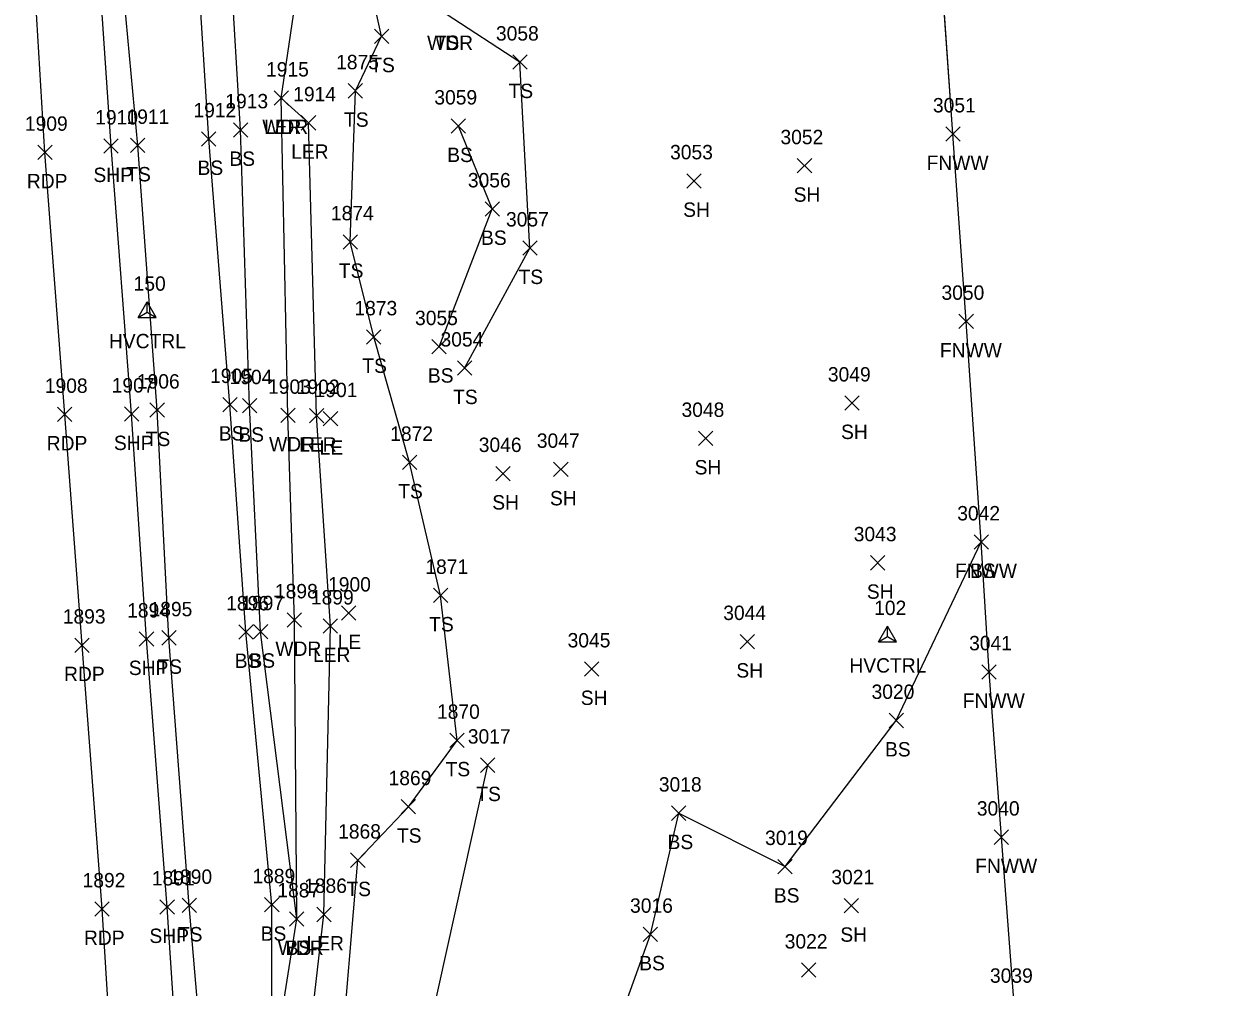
# Model space of a CAD drawing. Extents: x 1650221 to 1650634, y 244606 to 249996.
# Drawn here: x 1650455.2 to 1650620.5, y 244998.2 to 245132.2 of the extents above; entities that cross this region are included whole.
import ezdxf

# ---------------------------------------------------------------- set-up
doc = ezdxf.new("R2010")
doc.units = 0
for name, color, linetype in [('C_A', 7, 'Continuous'), ('C_I', 7, 'Continuous'), ('CPSM', 7, 'Continuous'), ('L_A', 7, 'Continuous'), ('L_I', 7, 'Continuous'), ('L_TIC', 7, 'Continuous'), ('LARO', 7, 'Continuous'), ('LAWA', 7, 'Continuous'), ('LELB', 7, 'Continuous'), ('LFNC', 7, 'Continuous'), ('LSOGP', 7, 'Continuous'), ('P_A', 7, 'Continuous'), ('P_I', 7, 'Continuous'), ('P_TIC', 7, 'Continuous'), ('PET', 7, 'Continuous'), ('PSP', 7, 'Continuous')]:
    doc.layers.add(name, color=color, linetype=linetype)

msp = doc.modelspace()

# ---------------------------------------------------------------- linework, layer by layer
at = {"layer": 'CPSM'}
for p, q in [((1650471.11, 245091.36), (1650472.36, 245093.53)), ((1650473.61, 245091.36), (1650472.36, 245093.53)), ((1650472.36, 245092.08), (1650472.36, 245093.53)), ((1650471.11, 245091.36), (1650472.36, 245092.08)), ((1650471.11, 245091.36), (1650473.61, 245091.36)), ((1650472.36, 245092.08), (1650472.36, 245092.08)), ((1650472.36, 245092.08), (1650473.61, 245091.36)), ((1650574.01, 245046.27), (1650575.26, 245048.43)), ((1650576.51, 245046.27), (1650575.26, 245048.43)), ((1650575.26, 245046.99), (1650575.26, 245048.43)), ((1650574.01, 245046.27), (1650575.26, 245046.99)), ((1650575.26, 245046.99), (1650575.26, 245046.99)), ((1650575.26, 245046.99), (1650576.51, 245046.27)), ((1650574.01, 245046.27), (1650576.51, 245046.27))]:
    msp.add_line(p, q, dxfattribs=at)
at = {"layer": 'L_TIC'}
for points in [[(1650503.95, 245129.46), (1650505.95, 245131.46)], [(1650505.95, 245129.46), (1650503.95, 245131.46)], [(1650523.17, 245125.86), (1650525.17, 245127.86)], [(1650525.17, 245125.86), (1650523.17, 245127.86)], [(1650490, 245120.86), (1650492, 245122.86)], [(1650492, 245120.86), (1650490, 245122.86)], [(1650490, 245120.86), (1650492, 245122.86)], [(1650492, 245120.86), (1650490, 245122.86)], [(1650500.31, 245121.87), (1650502.31, 245123.87)], [(1650502.31, 245121.87), (1650500.31, 245123.87)], [(1650493.78, 245117.42), (1650495.78, 245119.42)], [(1650495.78, 245117.42), (1650493.78, 245119.42)], [(1650484.35, 245116.44), (1650486.35, 245118.44)], [(1650486.35, 245116.44), (1650484.35, 245118.44)], [(1650514.62, 245116.97), (1650516.62, 245118.97)], [(1650516.62, 245116.97), (1650514.62, 245118.97)], [(1650583.33, 245115.87), (1650585.33, 245117.87)], [(1650585.33, 245115.87), (1650583.33, 245117.87)], [(1650470.05, 245114.28), (1650472.05, 245116.28)], [(1650472.05, 245114.28), (1650470.05, 245116.28)], [(1650479.92, 245115.18), (1650481.92, 245117.18)], [(1650481.92, 245115.18), (1650479.92, 245117.18)], [(1650562.71, 245111.45), (1650564.71, 245113.45)], [(1650564.71, 245111.45), (1650562.71, 245113.45)], [(1650547.37, 245109.35), (1650549.37, 245111.35)], [(1650549.37, 245109.35), (1650547.37, 245111.35)], [(1650519.32, 245105.45), (1650521.32, 245107.45)], [(1650521.32, 245105.45), (1650519.32, 245107.45)], [(1650499.59, 245100.87), (1650501.59, 245102.87)], [(1650501.59, 245100.87), (1650499.59, 245102.87)], [(1650524.56, 245100.01), (1650526.56, 245102.01)], [(1650526.56, 245100.01), (1650524.56, 245102.01)], [(1650585.18, 245089.82), (1650587.18, 245091.82)], [(1650587.18, 245089.82), (1650585.18, 245091.82)], [(1650502.85, 245087.66), (1650504.85, 245089.66)], [(1650504.85, 245087.66), (1650502.85, 245089.66)], [(1650511.93, 245086.3), (1650513.93, 245088.3)], [(1650513.93, 245086.3), (1650511.93, 245088.3)], [(1650515.47, 245083.32), (1650517.47, 245085.32)], [(1650517.47, 245083.32), (1650515.47, 245085.32)], [(1650472.75, 245077.48), (1650474.75, 245079.48)], [(1650474.75, 245077.48), (1650472.75, 245079.48)], [(1650482.87, 245078.25), (1650484.87, 245080.25)], [(1650484.87, 245078.25), (1650482.87, 245080.25)], [(1650485.59, 245078.09), (1650487.59, 245080.09)], [(1650487.59, 245078.09), (1650485.59, 245080.09)], [(1650569.3, 245078.46), (1650571.3, 245080.46)], [(1650571.3, 245078.46), (1650569.3, 245080.46)], [(1650490.93, 245076.75), (1650492.93, 245078.75)], [(1650492.93, 245076.75), (1650490.93, 245078.75)], [(1650494.91, 245076.72), (1650496.91, 245078.72)], [(1650496.91, 245076.72), (1650494.91, 245078.72)], [(1650496.84, 245076.29), (1650498.84, 245078.29)], [(1650498.84, 245076.29), (1650496.84, 245078.29)], [(1650548.96, 245073.54), (1650550.96, 245075.54)], [(1650550.96, 245073.54), (1650548.96, 245075.54)], [(1650507.84, 245070.21), (1650509.84, 245072.21)], [(1650509.84, 245070.21), (1650507.84, 245072.21)], [(1650528.85, 245069.24), (1650530.85, 245071.24)], [(1650530.85, 245069.24), (1650528.85, 245071.24)], [(1650520.83, 245068.66), (1650522.83, 245070.66)], [(1650522.83, 245068.66), (1650520.83, 245070.66)], [(1650587.27, 245059.15), (1650589.27, 245061.15)], [(1650589.27, 245059.15), (1650587.27, 245061.15)], [(1650587.27, 245059.15), (1650589.27, 245061.15)], [(1650589.27, 245059.15), (1650587.27, 245061.15)], [(1650572.89, 245056.25), (1650574.89, 245058.25)], [(1650574.89, 245056.25), (1650572.89, 245058.25)], [(1650512.14, 245051.72), (1650514.14, 245053.72)], [(1650514.14, 245051.72), (1650512.14, 245053.72)], [(1650499.35, 245049.26), (1650501.35, 245051.26)], [(1650501.35, 245049.26), (1650499.35, 245051.26)], [(1650491.82, 245048.31), (1650493.82, 245050.31)], [(1650493.82, 245048.31), (1650491.82, 245050.31)], [(1650485.09, 245046.64), (1650487.09, 245048.64)], [(1650487.09, 245046.64), (1650485.09, 245048.64)], [(1650487.13, 245046.67), (1650489.13, 245048.67)], [(1650489.13, 245046.67), (1650487.13, 245048.67)], [(1650496.83, 245047.46), (1650498.83, 245049.46)], [(1650498.83, 245047.46), (1650496.83, 245049.46)], [(1650474.38, 245045.82), (1650476.38, 245047.82)], [(1650476.38, 245045.82), (1650474.38, 245047.82)], [(1650554.75, 245045.3), (1650556.75, 245047.3)], [(1650556.75, 245045.3), (1650554.75, 245047.3)], [(1650533.13, 245041.49), (1650535.13, 245043.49)], [(1650535.13, 245041.49), (1650533.13, 245043.49)], [(1650588.36, 245041.09), (1650590.36, 245043.09)], [(1650590.36, 245041.09), (1650588.36, 245043.09)], [(1650575.46, 245034.33), (1650577.46, 245036.33)], [(1650577.46, 245034.33), (1650575.46, 245036.33)], [(1650514.42, 245031.57), (1650516.42, 245033.57)], [(1650516.42, 245031.57), (1650514.42, 245033.57)], [(1650518.69, 245028.12), (1650520.69, 245030.12)], [(1650520.69, 245028.12), (1650518.69, 245030.12)], [(1650507.66, 245022.34), (1650509.66, 245024.34)], [(1650509.66, 245022.34), (1650507.66, 245024.34)], [(1650545.24, 245021.45), (1650547.24, 245023.45)], [(1650547.24, 245021.45), (1650545.24, 245023.45)], [(1650590.08, 245018.11), (1650592.08, 245020.11)], [(1650592.08, 245018.11), (1650590.08, 245020.11)], [(1650500.64, 245014.91), (1650502.64, 245016.91)], [(1650502.64, 245014.91), (1650500.64, 245016.91)], [(1650560.01, 245014.02), (1650562.01, 245016.02)], [(1650562.01, 245014.02), (1650560.01, 245016.02)], [(1650477.22, 245008.62), (1650479.22, 245010.62)], [(1650479.22, 245008.62), (1650477.22, 245010.62)], [(1650488.69, 245008.71), (1650490.69, 245010.71)], [(1650490.69, 245008.71), (1650488.69, 245010.71)], [(1650569.21, 245008.57), (1650571.21, 245010.57)], [(1650571.21, 245008.57), (1650569.21, 245010.57)], [(1650492.15, 245006.74), (1650494.15, 245008.74)], [(1650494.15, 245006.74), (1650492.15, 245008.74)], [(1650492.15, 245006.74), (1650494.15, 245008.74)], [(1650494.15, 245006.74), (1650492.15, 245008.74)], [(1650495.92, 245007.36), (1650497.92, 245009.36)], [(1650497.92, 245007.36), (1650495.92, 245009.36)], [(1650541.3, 245004.6), (1650543.3, 245006.6)], [(1650543.3, 245004.6), (1650541.3, 245006.6)], [(1650563.3, 244999.63), (1650565.3, 245001.63)], [(1650565.3, 244999.63), (1650563.3, 245001.63)]]:
    msp.add_lwpolyline(points, dxfattribs=at)
at = {"layer": 'LARO'}
msp.add_lwpolyline([(1650518.65, 244690.58), (1650512.53, 244717.67), (1650511.45, 244754.99), (1650506.03, 244803.57), (1650503.39, 244847.38), (1650499.94, 244892.94), (1650496.08, 244933.34), (1650493.78, 244980.84), (1650496.92, 245008.36), (1650497.83, 245048.46), (1650495.91, 245077.72), (1650494.78, 245118.42), (1650491, 245121.86), (1650493.61, 245139.73)], dxfattribs=at)
at = {"layer": 'LAWA'}
msp.add_lwpolyline([(1650532.93, 244639.7), (1650524.86, 244673.45), (1650514.54, 244690.35), (1650510.25, 244717.67), (1650508.53, 244755.66), (1650503.06, 244803.5), (1650499.99, 244846.46), (1650496.47, 244893.78), (1650492.54, 244932.91), (1650488.72, 244979.52), (1650493.15, 245007.74), (1650492.82, 245049.31), (1650491.93, 245077.75), (1650491, 245121.86)], dxfattribs=at)
at = {"layer": 'LELB'}
for points in [[(1650489.71, 244991.22), (1650489.69, 245009.71), (1650486.09, 245047.64), (1650483.87, 245079.25), (1650480.92, 245116.18), (1650479.42, 245140.42), (1650476.29, 245187.3), (1650474, 245221.05), (1650469.02, 245258.31), (1650465.71, 245285.05), (1650462.26, 245315.54), (1650460.48, 245356.55), (1650462.16, 245378.82), (1650455.67, 245427.55), (1650451.48, 245462.76), (1650449.79, 245512.44), (1650449.11, 245548.12), (1650443.42, 245590.47), (1650442.32, 245632.05), (1650435.43, 245684.43)], [(1650493.15, 245007.74), (1650488.13, 245047.67), (1650486.59, 245079.09), (1650485.35, 245117.44), (1650483.97, 245140), (1650485.34, 245188.31), (1650482.43, 245221.37), (1650477.25, 245258), (1650473.1, 245285.62), (1650468.47, 245315.46), (1650468.65, 245355.64), (1650472.97, 245377.88), (1650463.98, 245429.04), (1650464.45, 245462.11), (1650460.79, 245514.67), (1650465.46, 245547.92), (1650447.43, 245596.3), (1650450.46, 245632.25)], [(1650513.46, 244857.93), (1650507.41, 244878.18), (1650510.15, 244893.51), (1650513.91, 244913.62), (1650507.18, 244927.34), (1650499.76, 244934.69), (1650501.94, 244958.86), (1650499.18, 244986.61), (1650501.64, 245015.91), (1650508.66, 245023.34), (1650515.42, 245032.57), (1650513.14, 245052.72), (1650508.84, 245071.21), (1650503.85, 245088.66), (1650500.59, 245101.87), (1650501.31, 245122.87), (1650504.95, 245130.46), (1650502.44, 245141.72)], [(1650505.23, 244636.62), (1650502.16, 244675.85), (1650500.4, 244713.01), (1650496.37, 244756.26), (1650493.25, 244801.26), (1650489.44, 244848.53), (1650486.4, 244894.8), (1650483.54, 244931.88), (1650480.85, 244978.69), (1650478.22, 245009.62), (1650475.38, 245046.82), (1650473.75, 245078.48), (1650471.05, 245115.28), (1650468.74, 245140.33)], [(1650516.47, 245084.32), (1650525.56, 245101.01), (1650524.17, 245126.86), (1650513.9, 245133.55)], [(1650512.93, 245087.3), (1650520.32, 245106.45), (1650515.62, 245117.97)], [(1650558.39, 244731), (1650560.16, 244746.89), (1650556.87, 244759.84), (1650538.74, 244776.67), (1650535.72, 244806.75), (1650532.14, 244826.66), (1650527.65, 244861.29), (1650520.49, 244892.39), (1650525.9, 244912.47), (1650527.83, 244939.42), (1650532.34, 244967.74), (1650532.66, 244978.77), (1650542.3, 245005.6), (1650546.24, 245022.45), (1650561.01, 245015.02), (1650576.46, 245035.33), (1650588.27, 245060.15)], [(1650511.55, 244940.43), (1650510.61, 244965.44), (1650510.63, 244988.08), (1650519.69, 245029.12)]]:
    msp.add_lwpolyline(points, dxfattribs=at)
at = {"layer": 'LFNC'}
msp.add_lwpolyline([(1650620.51, 244617.69), (1650617.31, 244662.42), (1650615.31, 244691.34), (1650613.19, 244720.04), (1650611.29, 244742.22), (1650608.76, 244769.54), (1650606.56, 244796.09), (1650605.06, 244817.05), (1650603.34, 244839.66), (1650601.74, 244864.61), (1650599.88, 244891.09), (1650599, 244907.23), (1650598.09, 244925.6), (1650595.48, 244961.16), (1650593.81, 244982.84), (1650592.83, 244995.87), (1650591.08, 245019.11), (1650589.36, 245042.09), (1650588.27, 245060.15), (1650586.18, 245090.82), (1650584.33, 245116.87), (1650580.12, 245176.92)], dxfattribs=at)
at = {"layer": 'LSOGP'}
msp.add_lwpolyline([(1650601.74, 244864.61), (1650599.88, 244891.09), (1650599, 244907.23), (1650598.09, 244925.6), (1650595.48, 244961.16), (1650592.83, 244995.87), (1650591.08, 245019.11), (1650589.36, 245042.09), (1650588.27, 245060.15), (1650586.18, 245090.82), (1650584.33, 245116.87), (1650579.44, 245186.98)], dxfattribs=at)
at = {"layer": 'P_TIC'}
for points in [[(1650466.35, 245114.19), (1650468.35, 245116.19)], [(1650468.35, 245114.19), (1650466.35, 245116.19)], [(1650457.15, 245113.32), (1650459.15, 245115.32)], [(1650459.15, 245113.32), (1650457.15, 245115.32)], [(1650459.91, 245076.88), (1650461.91, 245078.88)], [(1650461.91, 245076.88), (1650459.91, 245078.88)], [(1650469.2, 245076.93), (1650471.2, 245078.93)], [(1650471.2, 245076.93), (1650469.2, 245078.93)], [(1650462.32, 245044.8), (1650464.32, 245046.8)], [(1650464.32, 245044.8), (1650462.32, 245046.8)], [(1650471.27, 245045.65), (1650473.27, 245047.65)], [(1650473.27, 245045.65), (1650471.27, 245047.65)], [(1650465.09, 245008.13), (1650467.09, 245010.13)], [(1650467.09, 245008.13), (1650465.09, 245010.13)], [(1650474.14, 245008.4), (1650476.14, 245010.4)], [(1650476.14, 245008.4), (1650474.14, 245010.4)]]:
    msp.add_lwpolyline(points, dxfattribs=at)
at = {"layer": 'PET'}
msp.add_lwpolyline([(1650493.02, 244636.16), (1650490.06, 244675.27), (1650487.56, 244709.93), (1650484.05, 244756.69), (1650480.76, 244799.76), (1650477.49, 244848.34), (1650473.97, 244894.14), (1650471.41, 244931.35), (1650468.1, 244977.08), (1650466.09, 245009.13), (1650463.32, 245045.8), (1650460.91, 245077.88), (1650458.15, 245114.32), (1650456.62, 245139.84)], dxfattribs=at)
at = {"layer": 'PSP'}
msp.add_lwpolyline([(1650502.02, 244636.4), (1650499, 244675.82), (1650496.5, 244711.9), (1650492.99, 244756.49), (1650489.99, 244801), (1650486.51, 244848.42), (1650483.1, 244894.51), (1650480.52, 244931.79), (1650477.17, 244978.41), (1650475.14, 245009.4), (1650472.27, 245046.65), (1650470.2, 245077.93), (1650467.35, 245115.19), (1650465.66, 245140.38)], dxfattribs=at)

# ---------------------------------------------------------------- texts
at = {"layer": 'C_A'}
for p in [(1650467.05, 245087.08), (1650569.95, 245041.99)]:
    msp.add_text('HVCTRL', height=2, dxfattribs=at).set_placement(p)
at = {"layer": 'C_I'}
for s, p in [('150', (1650470.48, 245095.08)), ('102', (1650573.39, 245049.99))]:
    msp.add_text(s, height=2, dxfattribs=at).set_placement(p)
at = {"layer": 'L_A'}
for s, p in [('WDR', (1650511.26, 245128.55)), ('TS', (1650512.3, 245128.55)), ('TS', (1650503.36, 245125.46)), ('TS', (1650522.58, 245121.86)), ('TS', (1650499.72, 245117.87)), ('WDR', (1650488.36, 245116.86)), ('LER', (1650488.59, 245116.86)), ('BS', (1650483.79, 245112.44)), ('LER', (1650492.37, 245113.42)), ('BS', (1650514.06, 245112.97)), ('BS', (1650479.36, 245111.18)), ('FNWW', (1650580.68, 245111.87)), ('TS', (1650469.46, 245110.28)), ('SH', (1650562.2, 245107.45)), ('SH', (1650546.85, 245105.35)), ('BS', (1650518.76, 245101.45)), ('TS', (1650499, 245096.87)), ('TS', (1650523.97, 245096.01)), ('FNWW', (1650582.53, 245085.82)), ('TS', (1650502.26, 245083.66)), ('BS', (1650511.37, 245082.3)), ('TS', (1650514.88, 245079.32)), ('BS', (1650482.32, 245074.25)), ('BS', (1650485.03, 245074.09)), ('SH', (1650568.79, 245074.46)), ('TS', (1650472.16, 245073.48)), ('WDR', (1650489.3, 245072.75)), ('LER', (1650493.49, 245072.72)), ('LE', (1650496.32, 245072.29)), ('SH', (1650548.44, 245069.54)), ('TS', (1650507.25, 245066.21)), ('SH', (1650520.32, 245064.66)), ('SH', (1650528.34, 245065.24)), ('FNWW', (1650584.62, 245055.15)), ('BS', (1650586.72, 245055.15)), ('SH', (1650572.38, 245052.25)), ('TS', (1650511.55, 245047.72)), ('WDR', (1650490.18, 245044.31)), ('LE', (1650498.84, 245045.26)), ('BS', (1650484.53, 245042.64)), ('BS', (1650486.57, 245042.67)), ('LER', (1650495.41, 245043.46)), ('TS', (1650473.79, 245041.82)), ('SH', (1650554.24, 245041.3)), ('SH', (1650532.62, 245037.49)), ('FNWW', (1650585.71, 245037.09)), ('BS', (1650574.9, 245030.33)), ('TS', (1650513.83, 245027.57)), ('TS', (1650518.1, 245024.12)), ('TS', (1650507.07, 245018.34)), ('BS', (1650544.68, 245017.45)), ('FNWW', (1650587.43, 245014.11)), ('TS', (1650500.05, 245010.91)), ('BS', (1650559.45, 245010.02)), ('TS', (1650476.63, 245004.62)), ('BS', (1650488.13, 245004.71)), ('LER', (1650494.5, 245003.36)), ('SH', (1650568.69, 245004.57)), ('WDR', (1650490.51, 245002.74)), ('BS', (1650491.59, 245002.74)), ('BS', (1650540.74, 245000.6))]:
    msp.add_text(s, height=2, dxfattribs=at).set_placement(p)
at = {"layer": 'L_I'}
for s, p in [('3058', (1650520.83, 245129.86)), ('1875', (1650498.62, 245125.87)), ('1915', (1650488.88, 245124.86)), ('1915', (1650488.88, 245124.86)), ('1913', (1650483.22, 245120.44)), ('1914', (1650492.66, 245121.42)), ('3059', (1650512.27, 245120.97)), ('1912', (1650478.79, 245119.18)), ('3051', (1650581.56, 245119.87)), ('1911', (1650469.49, 245118.28)), ('3052', (1650560.37, 245115.45)), ('3053', (1650545.03, 245113.35)), ('3056', (1650516.93, 245109.45)), ('1874', (1650497.9, 245104.87)), ('3057', (1650522.23, 245104.01)), ('3050', (1650582.75, 245093.82)), ('1873', (1650501.16, 245091.66)), ('3055', (1650509.59, 245090.3)), ('3054', (1650513.13, 245087.32)), ('3049', (1650566.96, 245082.46)), ('1906', (1650470.93, 245081.48)), ('1905', (1650481.1, 245082.25)), ('1904', (1650483.81, 245082.09)), ('1903', (1650489.16, 245080.75)), ('1902', (1650493.14, 245080.72)), ('1901', (1650495.63, 245080.29)), ('3048', (1650546.62, 245077.54)), ('1872', (1650506.14, 245074.21)), ('3046', (1650518.44, 245072.66)), ('3047', (1650526.51, 245073.24)), ('3042', (1650584.94, 245063.15)), ('3042', (1650584.94, 245063.15)), ('3043', (1650570.55, 245060.25)), ('1871', (1650511.02, 245055.72)), ('1900', (1650497.5, 245053.26)), ('1898', (1650490.12, 245052.31)), ('1899', (1650495.12, 245051.46)), ('1895', (1650472.69, 245049.82)), ('1896', (1650483.34, 245050.64)), ('1897', (1650485.44, 245050.67)), ('3044', (1650552.42, 245049.3)), ('3045', (1650530.79, 245045.49)), ('3041', (1650586.59, 245045.09)), ('3020', (1650573.03, 245038.33)), ('1870', (1650512.64, 245035.57)), ('3017', (1650516.92, 245032.12)), ('1869', (1650505.91, 245026.34)), ('3018', (1650543.47, 245025.45)), ('3040', (1650587.66, 245022.11)), ('1868', (1650498.9, 245018.91)), ('3019', (1650558.23, 245018.02)), ('1890', (1650475.44, 245012.62)), ('1889', (1650486.99, 245012.71)), ('1886', (1650494.17, 245011.36)), ('3021', (1650567.44, 245012.57)), ('1887', (1650490.45, 245010.74)), ('1887', (1650490.45, 245010.74)), ('3016', (1650539.47, 245008.6)), ('3022', (1650560.96, 245003.63)), ('3039', (1650589.49, 244998.87)), ('3039', (1650589.49, 244998.87))]:
    msp.add_text(s, height=2, dxfattribs=at).set_placement(p)
at = {"layer": 'P_A'}
for s, p in [('RDP', (1650455.64, 245109.32)), ('SHP', (1650464.89, 245110.19)), ('RDP', (1650458.4, 245072.88)), ('SHP', (1650467.74, 245072.93)), ('SHP', (1650469.81, 245041.65)), ('RDP', (1650460.81, 245040.8)), ('RDP', (1650463.58, 245004.13)), ('SHP', (1650472.68, 245004.4))]:
    msp.add_text(s, height=2, dxfattribs=at).set_placement(p)
at = {"layer": 'P_I'}
for s, p in [('1909', (1650455.37, 245117.32)), ('1910', (1650465.14, 245118.19)), ('1908', (1650458.14, 245080.88)), ('1907', (1650467.43, 245080.93)), ('1894', (1650469.58, 245049.65)), ('1893', (1650460.63, 245048.8)), ('1892', (1650463.39, 245012.13)), ('1891', (1650473.02, 245012.4))]:
    msp.add_text(s, height=2, dxfattribs=at).set_placement(p)

doc.saveas('drawing.dxf')
